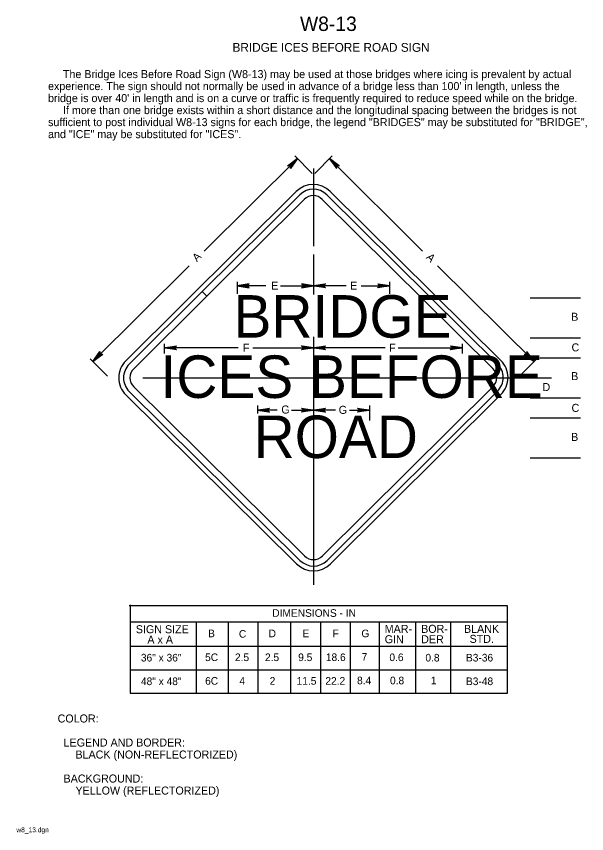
# Model space of a CAD drawing. Extents: x 0.013 to 0.191, y 0.004 to 0.259.
import ezdxf

# ---------------------------------------------------------------- set-up
doc = ezdxf.new("R2010")
doc.units = 0
for name, color, linetype in [('1', 7, 'Continuous'), ('2', 7, 'Continuous'), ('3', 7, 'Continuous')]:
    doc.layers.add(name, color=color, linetype=linetype)

# ---------------------------------------------------------------- blocks, each defined once
blk = doc.blocks.new('RARROW')
at = {"layer": '3'}
for p, q in [((-2.156, 0.28500000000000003), (-2.2665, 0.384625)), ((-2.2665, 0.384625), (0, 0)), ((0, 0), (-2.2665, -0.379125)), ((-2.156, 0.28500000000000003), (-2.075625, 0.12075)), ((0, 0), (-2.156, 0.28500000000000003)), ((-2.14975, -0.2705), (0, 0)), ((-2.075625, 0.12075), (0, 0)), ((0, 0), (-2.074, -0.108)), ((-2.2665, -0.379125), (-2.14975, -0.2705)), ((-2.074, -0.108), (-2.14975, -0.2705))]:
    blk.add_line(p, q, dxfattribs=at)

msp = doc.modelspace()

# ---------------------------------------------------------------- linework, layer by layer
at = {"layer": '1'}
for p, q in [((0.1053605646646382, 0.21161191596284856), (0.1053605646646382, 0.18736191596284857)), ((0.07068008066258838, 0.17315606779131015), (0.10107444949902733, 0.2033491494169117)), ((0.10248395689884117, 0.2019302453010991), (0.07210136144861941, 0.17174885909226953)), ((0.16141532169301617, 0.1491645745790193), (0.10811729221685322, 0.20193490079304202)), ((0.10952445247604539, 0.20335613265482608), (0.16282248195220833, 0.15058580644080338)), ((0.1053605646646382, 0.18472039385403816), (0.1053605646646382, 0.17223691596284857)), ((0.04786371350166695, 0.15049080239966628), (0.07068008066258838, 0.17315606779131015)), ((0.07210136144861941, 0.17174885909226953), (0.049273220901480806, 0.14907189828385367)), ((0.07068008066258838, 0.17315606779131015), (0.07210136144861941, 0.17174885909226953)), ((0.07210136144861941, 0.17174885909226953), (0.07068008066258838, 0.17315606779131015)), ((0.1053605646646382, 0.1590230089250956), (0.1053605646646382, 0.08161999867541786)), ((0.05209223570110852, 0.1462340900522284), (0.1748692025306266, 0.1462340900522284)), ((0.04927791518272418, 0.14339162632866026), (0.10257594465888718, 0.09062130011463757)), ((0.10820927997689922, 0.09062595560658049), (0.16142001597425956, 0.14348430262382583)), ((0.10116878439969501, 0.08920006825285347), (0.04787075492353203, 0.1419703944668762)), ((0.16282952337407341, 0.14206539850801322), (0.10961878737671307, 0.08920705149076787)), ((0.0878605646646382, 0.1376270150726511), (0.0878605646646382, 0.1351340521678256)), ((0.1228605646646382, 0.1376270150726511), (0.1228605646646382, 0.1328785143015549))]:
    msp.add_line(p, q, dxfattribs=at)
for centre, radius, start, end in [((0.10530297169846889, 0.19909243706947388), 0.0075, 45.285051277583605, 134.80964927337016), ((0.10530297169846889, 0.19909243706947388), 0.005999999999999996, 45.285051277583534, 134.8096492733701), ((0.10530297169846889, 0.19909243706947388), 0.004000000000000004, 45.285051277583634, 134.80964927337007), ((0.15860100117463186, 0.1463221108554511), 0.006000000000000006, 314.8096492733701, 45.285051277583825), ((0.15860100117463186, 0.1463221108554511), 0.0075, 314.8096492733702, 45.28505127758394), ((0.05209223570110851, 0.14623409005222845), 0.006000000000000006, 134.80964927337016, 225.28505127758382), ((0.05209223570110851, 0.14623409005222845), 0.004000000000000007, 134.80964927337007, 225.28505127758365), ((0.15860100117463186, 0.1463221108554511), 0.0040000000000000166, 314.8096492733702, 45.28505127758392), ((0.1053902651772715, 0.09346376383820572), 0.003999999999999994, 225.28505127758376, 314.8096492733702), ((0.1053902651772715, 0.09346376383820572), 0.0075, 225.2850512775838, 314.80964927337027), ((0.1053902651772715, 0.09346376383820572), 0.006000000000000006, 225.28505127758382, 314.8096492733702)]:
    msp.add_arc(centre, radius, start, end, dxfattribs=at)
at = {"layer": '3'}
for p, q in [((0.0712652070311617, 0.18576837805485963), (0.10039481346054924, 0.21464171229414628)), ((0.10497065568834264, 0.21002525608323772), (0.09951484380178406, 0.21552949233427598)), ((0.10575047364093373, 0.21002525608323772), (0.11120628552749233, 0.21552949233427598)), ((0.13945592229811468, 0.18576837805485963), (0.11032631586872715, 0.21464171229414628)), ((0.04680658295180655, 0.15155498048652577), (0.10001731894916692, 0.2044133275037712)), ((0.1105798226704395, 0.20442205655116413), (0.16387785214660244, 0.15165173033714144)), ((0.06661774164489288, 0.18116179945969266), (0.0365011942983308, 0.15131020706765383)), ((0.14410338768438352, 0.18116179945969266), (0.17421993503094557, 0.15131020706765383)), ((0.08160730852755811, 0.17248025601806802), (0.08160730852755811, 0.17623025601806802)), ((0.12916819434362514, 0.17248025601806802), (0.12916819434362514, 0.17623025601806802)), ((0.09046412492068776, 0.17498025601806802), (0.08155293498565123, 0.17498025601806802)), ((0.09512695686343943, 0.17498025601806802), (0.1053605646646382, 0.17498025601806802)), ((0.11559417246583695, 0.17498025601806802), (0.1053605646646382, 0.17498025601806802)), ((0.12025700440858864, 0.17498025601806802), (0.12916819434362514, 0.17498025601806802)), ((0.17300406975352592, 0.1712340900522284), (0.18875406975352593, 0.1712340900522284)), ((0.17300406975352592, 0.1587340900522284), (0.18875406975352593, 0.1587340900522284)), ((0.05886056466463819, 0.15386191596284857), (0.05886056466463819, 0.1568470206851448)), ((0.15186056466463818, 0.15386191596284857), (0.15186056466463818, 0.1568470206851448)), ((0.08191816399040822, 0.15560359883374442), (0.05886056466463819, 0.15560359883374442)), ((0.0864773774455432, 0.15560359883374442), (0.1053605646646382, 0.15560359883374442)), ((0.1277175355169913, 0.15560359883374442), (0.1053605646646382, 0.15560359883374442)), ((0.13186227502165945, 0.15560359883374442), (0.15186056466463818, 0.15560359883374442)), ((0.04107703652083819, 0.14669375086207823), (0.035621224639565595, 0.15219798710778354)), ((0.1696440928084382, 0.14669375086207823), (0.1750999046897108, 0.15219798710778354)), ((0.17605555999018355, 0.1524840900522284), (0.18875406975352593, 0.1524840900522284)), ((0.17072446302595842, 0.1462340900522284), (0.17968220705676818, 0.1462340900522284)), ((0.046815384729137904, 0.14090447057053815), (0.1001134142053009, 0.08813414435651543)), ((0.11067591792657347, 0.08814287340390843), (0.16388665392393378, 0.1410012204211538)), ((0.17300406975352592, 0.1399840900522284), (0.18875406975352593, 0.1399840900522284)), ((0.09408026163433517, 0.13612332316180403), (0.0878605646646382, 0.13612332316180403)), ((0.09851586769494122, 0.13612332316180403), (0.1053605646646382, 0.13612332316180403)), ((0.11220526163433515, 0.13612332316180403), (0.1053605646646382, 0.13612332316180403)), ((0.11664086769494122, 0.13612332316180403), (0.1228605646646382, 0.13612332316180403)), ((0.17300406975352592, 0.1337340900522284), (0.18875406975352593, 0.1337340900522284)), ((0.17300406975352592, 0.12123409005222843), (0.18875406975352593, 0.12123409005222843)), ((0.047879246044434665, 0.07511024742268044), (0.1658779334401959, 0.07511024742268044)), ((0.048115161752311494, 0.07536897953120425), (0.048115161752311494, 0.04773524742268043)), ((0.1658779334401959, 0.07517869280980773), (0.1658779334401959, 0.04773524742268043)), ((0.1658779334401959, 0.0699841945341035), (0.048115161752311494, 0.0699841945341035)), ((0.0687379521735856, 0.0699841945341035), (0.0687379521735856, 0.04773524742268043)), ((0.08805412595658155, 0.0699841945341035), (0.08805412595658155, 0.04773524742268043)), ((0.13726083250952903, 0.0699841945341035), (0.13726083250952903, 0.04773524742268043)), ((0.14819400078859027, 0.0699841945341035), (0.14819400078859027, 0.04773524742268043)), ((0.048115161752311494, 0.062485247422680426), (0.1658779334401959, 0.062485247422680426)), ((0.048129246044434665, 0.055110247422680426), (0.16589201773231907, 0.055110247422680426)), ((0.04814333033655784, 0.04773524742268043), (0.16589201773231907, 0.04773524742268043))]:
    msp.add_line(p, q, dxfattribs=at)
for points in [[(0.07876516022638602, 0.0699841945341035), (0.07876516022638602, 0.04773524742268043)], [(0.09815779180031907, 0.0699841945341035), (0.09815779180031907, 0.04773524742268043)], [(0.10760088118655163, 0.0699841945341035), (0.10760088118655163, 0.04773524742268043)], [(0.11685088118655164, 0.0699841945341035), (0.11685088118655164, 0.04773524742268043)], [(0.12587587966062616, 0.0699841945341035), (0.12587587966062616, 0.04773524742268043)]]:
    msp.add_lwpolyline(points, dxfattribs=at)
msp.add_arc((0.05209223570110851, 0.14623409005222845), 0.0075, 134.80964927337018, 225.28505127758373, dxfattribs=at)

# ---------------------------------------------------------------- block references
for p, xscale, yscale, rotation in [((0.10039481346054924, 0.21464171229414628), 0.0016545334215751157, 0.0016366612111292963, 44.74685388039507), ((0.11032631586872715, 0.21464171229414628), 0.0016545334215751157, -0.0016366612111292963, 135.25314611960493), ((0.08155293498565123, 0.17498025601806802), 0.0016545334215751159, -0.0016366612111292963, 180), ((0.1053605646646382, 0.17498025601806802), 0.0016545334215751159, 0.0016366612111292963, 180), ((0.05886056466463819, 0.15560359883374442), 0.0016545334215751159, 0.0016366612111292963, 180), ((0.1053605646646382, 0.15560359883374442), 0.0016545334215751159, 0.0016366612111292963, 180), ((0.0365011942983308, 0.15131020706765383), 0.001654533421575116, 0.0016366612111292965, -135.25314611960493), ((0.17421993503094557, 0.15131020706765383), 0.001654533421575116, -0.0016366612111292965, -44.74685388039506), ((0.0878605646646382, 0.13612332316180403), 0.0016545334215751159, 0.0016366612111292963, 180), ((0.1053605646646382, 0.13612332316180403), 0.0016545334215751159, 0.0016366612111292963, 180)]:
    msp.add_blockref('RARROW', p, dxfattribs=dict(at, xscale=xscale, yscale=yscale, rotation=rotation))
at = {"layer": '3', "xscale": 0.0016545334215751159}
for p, yscale in [((0.1053605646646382, 0.17498025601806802), -0.0016366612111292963), ((0.12916819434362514, 0.17498025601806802), 0.0016366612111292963), ((0.1053605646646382, 0.15560359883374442), 0.0016366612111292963), ((0.15186056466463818, 0.15560359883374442), 0.0016366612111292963), ((0.1053605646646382, 0.13612332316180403), 0.0016366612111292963), ((0.1228605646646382, 0.13612332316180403), 0.0016366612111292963)]:
    msp.add_blockref('RARROW', p, dxfattribs=dict(at, yscale=yscale))

# ---------------------------------------------------------------- texts
at = {"layer": '1'}
for s, height, p in [('W8-13', 0.0045000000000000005, (0.10116545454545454, 0.2545)), ('BRIDGE ICES BEFORE ROAD SIGN', 0.00275025, (0.08010758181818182, 0.248)), ('COLOR:', 0.0024997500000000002, (0.025500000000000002, 0.038624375)), ('  LEGEND AND BORDER:', 0.0024997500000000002, (0.025500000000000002, 0.031124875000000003)), ('      BLACK (NON-REFLECTORIZED)', 0.0024997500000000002, (0.025500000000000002, 0.027375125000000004)), ('  BACKGROUND:', 0.0024997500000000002, (0.025500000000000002, 0.019875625)), ('      YELLOW (REFLECTORIZED)', 0.0024997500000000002, (0.025500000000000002, 0.016125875)), ('w8_13.dgn', 0.0015, (0.012625, 0.004375))]:
    msp.add_text(s, height=height, dxfattribs=at).set_placement(p)
at = {"layer": '2'}
for s, p in [('     The Bridge Ices Before Road Sign (W8-13) may be used at those bridges where icing is prevalent by actual', (0.02251589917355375, 0.23979256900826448)), ("experience. The sign should not normally be used in advance of a bridge less than 100' in length, unless the", (0.02251589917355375, 0.2360428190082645)), ("bridge is over 40' in length and is on a curve or traffic is frequently required to reduce speed while on the bridge.", (0.02251589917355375, 0.2322930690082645)), ('     If more than one bridge exists within a short distance and the longitudinal spacing between the bridges is not', (0.02251589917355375, 0.2285433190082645)), ('sufficient to post individual W8-13 signs for each bridge, the legend "BRIDGES" may be substituted for "BRIDGE",', (0.02251589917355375, 0.2247935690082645)), ('and "ICE" may be substituted for "ICES".', (0.02251589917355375, 0.22104381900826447))]:
    msp.add_text(s, height=0.0024997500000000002, dxfattribs=at).set_placement(p)
at = {"layer": '3'}
for s, height, rotation, p in [('A', 0.0025, 44.746853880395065, (0.06900583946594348, 0.18229510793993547)), ('A', 0.0025, 315.25314611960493, (0.14035725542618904, 0.18364119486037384)), ('E', 0.0025, 360, (0.11678832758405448, 0.17373025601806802)), ('F', 0.0025, 360, (0.08335996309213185, 0.15435359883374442)), ('F', 0.0025, 360, (0.1289751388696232, 0.15435359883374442)), ('B', 0.0024997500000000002, 360, (0.18580986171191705, 0.14550892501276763)), ('D', 0.0024997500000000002, 360, (0.1768513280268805, 0.14208951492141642)), ('C', 0.0024997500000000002, 360, (0.1859393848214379, 0.13558293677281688)), ('ROAD', 0.013271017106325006, 360, (0.0867017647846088, 0.12118580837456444)), ('B', 0.0024997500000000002, 360, (0.18580986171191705, 0.12651757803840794)), ('DIMENSIONS - IN', 0.0023752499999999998, 360, (0.0925166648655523, 0.07161024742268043)), ('E', 0.0023752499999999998, 360, (0.10191957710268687, 0.06523524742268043)), ('F', 0.0023752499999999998, 360, (0.11132588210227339, 0.06523524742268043)), ('2.5', 0.0023752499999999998, 360, (0.09023271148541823, 0.057797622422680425)), ('18.6', 0.0023752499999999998, 360, (0.10924116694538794, 0.057797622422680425)), ('2', 0.0023752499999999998, 360, (0.09169893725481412, 0.050422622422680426)), ('22.2', 0.0023752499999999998, 360, (0.10909078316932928, 0.050422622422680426)), ('0.8', 0.0023752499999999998, 360, (0.12926731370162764, 0.05054762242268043))]:
    msp.add_text(s, height=height, rotation=rotation, dxfattribs=at).set_placement(p)
for s, height, p in [('E', 0.0025, (0.09216310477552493, 0.17373025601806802)), ('BRIDGE', 0.013271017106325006, (0.0804167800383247, 0.15875832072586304)), ('B', 0.0024997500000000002, (0.18580986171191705, 0.16402747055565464)), ('C', 0.0024997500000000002, (0.1859393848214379, 0.15447318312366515)), ('ICES BEFORE', 0.013271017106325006, (0.057631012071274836, 0.13994238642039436)), ('G', 0.0025, (0.09533026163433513, 0.13508056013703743)), ('G', 0.0025, (0.11324802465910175, 0.13497694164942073)), ('SIGN SIZE', 0.0024997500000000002, (0.04991564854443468, 0.06648524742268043)), ('MAR-', 0.0024997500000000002, (0.1276086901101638, 0.06661024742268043)), ('BOR-', 0.0024997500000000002, (0.1389836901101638, 0.06661024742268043)), ('BLANK', 0.0024997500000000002, (0.15235869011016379, 0.06661024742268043)), ('B', 0.0023752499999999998, (0.07248121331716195, 0.06523524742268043)), ('C', 0.0023752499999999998, (0.08210221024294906, 0.06510502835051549)), ('D', 0.0023752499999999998, (0.09138167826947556, 0.06523524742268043)), ('G', 0.0023752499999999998, (0.12034721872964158, 0.06523524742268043)), ('A x A', 0.0024997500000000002, (0.05352740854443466, 0.06323549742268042)), ('GIN', 0.0024997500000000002, (0.1276086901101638, 0.06336024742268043)), ('DER', 0.0024997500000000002, (0.1389836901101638, 0.06336024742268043)), ('STD.', 0.0024997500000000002, (0.1541086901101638, 0.06348524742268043)), ('36" x 36"', 0.0023752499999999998, (0.05149965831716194, 0.057672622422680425)), ('5C', 0.0023752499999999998, (0.07154382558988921, 0.057797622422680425)), ('2.5', 0.0023752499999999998, (0.08085754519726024, 0.057797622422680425)), ('9.5', 0.0023752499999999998, (0.1006050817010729, 0.057797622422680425)), ('7', 0.0023752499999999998, (0.12041638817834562, 0.057922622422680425)), ('0.6', 0.0023752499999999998, (0.12908132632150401, 0.05779240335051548)), ('0.8', 0.0023752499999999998, (0.1403183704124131, 0.05766740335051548)), ('B3-36', 0.0023752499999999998, (0.15298511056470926, 0.057672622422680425)), ('48" x 48"', 0.0023752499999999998, (0.05151374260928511, 0.050297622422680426)), ('6C', 0.0023752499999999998, (0.07155790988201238, 0.050422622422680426)), ('4', 0.0023752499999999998, (0.08226079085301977, 0.050422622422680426)), ('11.5', 0.0023752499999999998, (0.10011532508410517, 0.050422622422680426)), ('8.4', 0.0023752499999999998, (0.1189797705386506, 0.050547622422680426)), ('1', 0.0023752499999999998, (0.14199584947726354, 0.050547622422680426)), ('B3-48', 0.0023752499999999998, (0.1529862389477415, 0.050297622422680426))]:
    msp.add_text(s, height=height, dxfattribs=at).set_placement(p)

doc.saveas('drawing.dxf')
